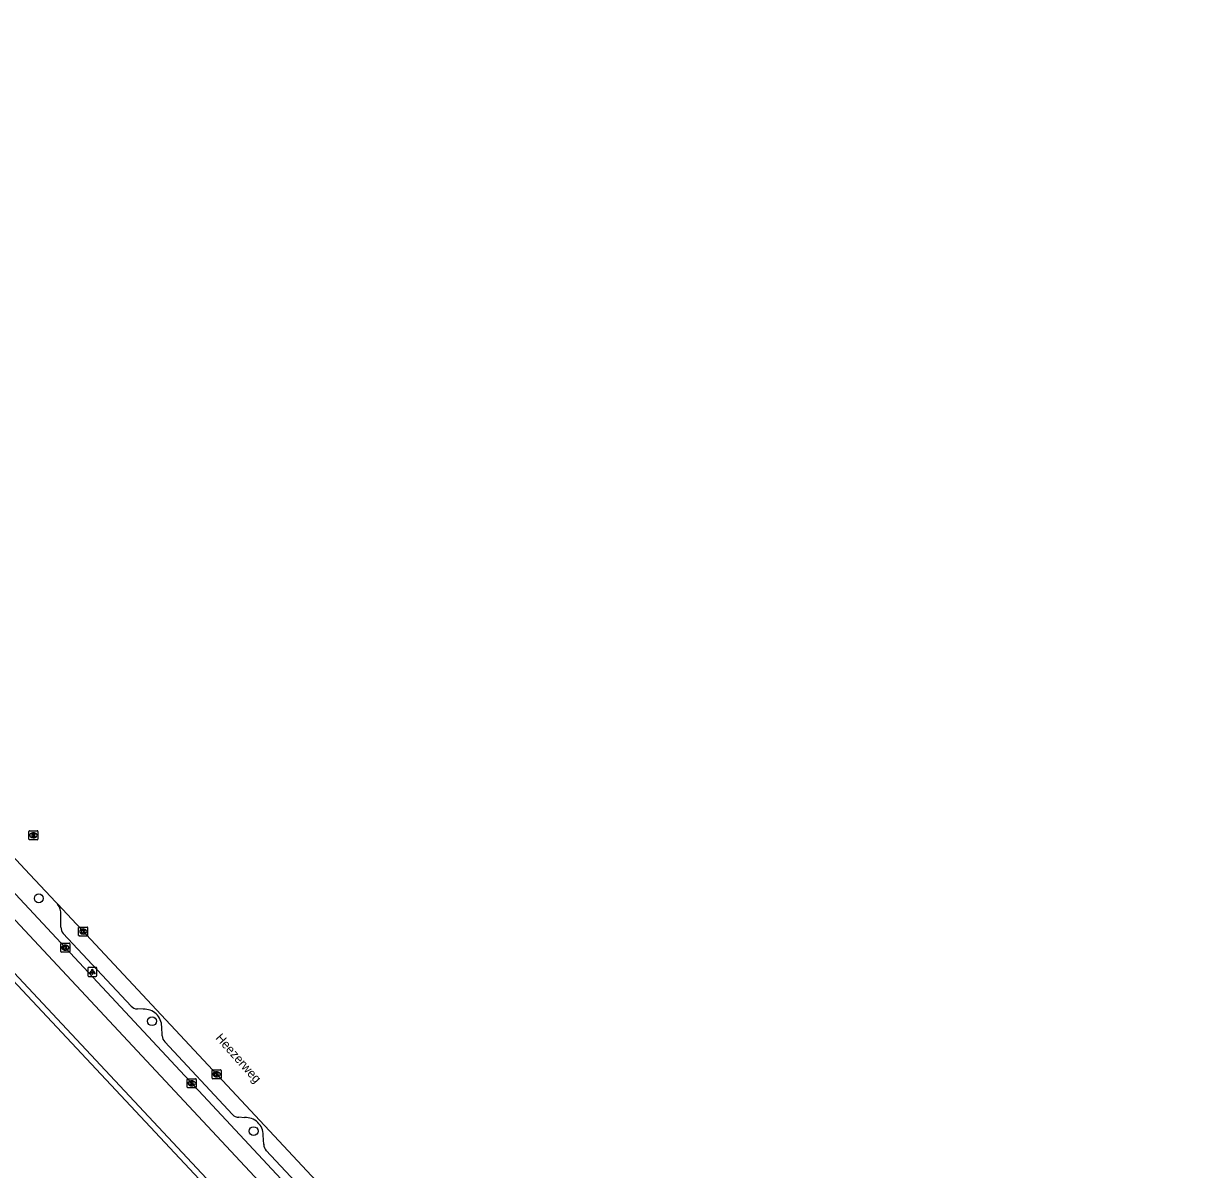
# Model space of a CAD drawing. Extents: x 162675 to 163482, y 379761 to 381227.
# Drawn here: x 163311.1 to 163442.5, y 381014.2 to 381141.4 of the extents above; entities that cross this region are included whole.
import ezdxf

# ---------------------------------------------------------------- set-up
doc = ezdxf.new("R2010")
doc.units = 0
for name, color, linetype in [('IMGEO_Boom', 7, 'Continuous'), ('IMGEO_Fietspad_gesloten', 7, 'Continuous'), ('IMGEO_Groenvoorziening', 7, 'Continuous'), ('IMGEO_Kolk', 7, 'Continuous'), ('IMGEO_Lichtpunt', 7, 'Continuous'), ('IMGEO_Openbare_ruimte_label', 7, 'Continuous'), ('IMGEO_Parkeervlak_open', 7, 'Continuous'), ('IMGEO_Rijbaan_lokaal_gesloten', 7, 'Continuous'), ('IMGEO_Rioolput', 7, 'Continuous'), ('IMGEO_Voetpad_open', 7, 'Continuous')]:
    doc.layers.add(name, color=color, linetype=linetype)

msp = doc.modelspace()

# ---------------------------------------------------------------- linework, layer by layer
at = {"layer": 'IMGEO_Boom'}
for centre in [(163312.75, 381044.24), (163325.33, 381030.6), (163336.61, 381018.4)]:
    msp.add_circle(centre, 0.489, dxfattribs=at)
at = {"layer": 'IMGEO_Fietspad_gesloten'}
for points in [[(163442.53, 380900.21), (163438.58, 380904.4), (163403.36, 380942.04), (163381.32, 380965.64), (163349.19, 381000), (163303.35, 381049.03), (163302.54, 381049.9), (163269.7, 381085.15), (163222.96, 381135.12), (163217.06, 381141.36)], [(163297.63, 381058.04), (163301.94, 381053.48), (163304.04, 381051.23), (163315.71, 381038.75), (163343.73, 381008.7), (163351.89, 381000), (163369.83, 380980.88), (163383.5, 380966.22), (163404.83, 380943.42), (163407.34, 380940.66), (163420.71, 380926.42), (163421.99, 380925.07)]]:
    msp.add_lwpolyline(points, dxfattribs=at)
at = {"layer": 'IMGEO_Groenvoorziening'}
msp.add_lwpolyline([(163366.04, 380975.19), (163307.1, 381038.09), (163305.72, 381038.49), (163302.71, 381038.33)], dxfattribs=at)
at = {"layer": 'IMGEO_Kolk'}
for p, q in [((163317.18, 381040.13), (163317.18, 381040.99)), ((163317.26, 381041.06), (163318.11, 381041.06)), ((163318.11, 381040.06), (163317.26, 381040.06)), ((163317.67, 381040.84), (163317.7, 381040.84)), ((163317.69, 381040.28), (163317.67, 381040.28)), ((163318.18, 381040.99), (163318.18, 381040.13)), ((163315.19, 381038.34), (163315.19, 381039.2)), ((163315.27, 381039.27), (163316.12, 381039.27)), ((163315.68, 381039.05), (163315.71, 381039.05)), ((163316.19, 381039.2), (163316.19, 381038.34)), ((163316.12, 381038.27), (163315.27, 381038.27)), ((163315.7, 381038.49), (163315.68, 381038.49)), ((163332, 381024.29), (163332, 381025.14)), ((163332.07, 381025.21), (163332.93, 381025.21)), ((163332.51, 381024.43), (163332.48, 381024.43)), ((163332.49, 381024.99), (163332.51, 381024.99)), ((163333, 381025.14), (163333, 381024.29)), ((163329.23, 381023.28), (163329.23, 381024.14)), ((163329.31, 381024.21), (163330.16, 381024.21)), ((163330.16, 381023.21), (163329.31, 381023.21)), ((163329.72, 381023.99), (163329.75, 381023.99)), ((163329.74, 381023.43), (163329.72, 381023.43)), ((163330.24, 381024.14), (163330.24, 381023.28)), ((163332.93, 381024.21), (163332.07, 381024.21))]:
    msp.add_line(p, q, dxfattribs=at)
for points in [[(163317.18, 381040.13), (163317.18, 381040.99)], [(163317.26, 381041.06), (163318.11, 381041.06)], [(163318.11, 381040.06), (163317.26, 381040.06)], [(163317.5, 381040.76), (163317.63, 381040.76), (163317.63, 381040.61), (163317.76, 381040.76), (163317.92, 381040.76), (163317.78, 381040.61), (163317.93, 381040.36), (163317.78, 381040.36), (163317.69, 381040.52), (163317.63, 381040.46), (163317.63, 381040.36), (163317.5, 381040.36), (163317.5, 381040.76)], [(163318.18, 381040.99), (163318.18, 381040.13)], [(163315.19, 381038.34), (163315.19, 381039.2)], [(163315.27, 381039.27), (163316.12, 381039.27)], [(163315.51, 381038.97), (163315.64, 381038.97), (163315.64, 381038.82), (163315.77, 381038.97), (163315.93, 381038.97), (163315.78, 381038.82), (163315.94, 381038.57), (163315.78, 381038.57), (163315.7, 381038.74), (163315.64, 381038.67), (163315.64, 381038.57), (163315.51, 381038.57), (163315.51, 381038.97)], [(163316.19, 381039.2), (163316.19, 381038.34)], [(163316.12, 381038.27), (163315.27, 381038.27)], [(163332, 381024.29), (163332, 381025.14)], [(163332.07, 381025.21), (163332.93, 381025.21)], [(163332.32, 381024.91), (163332.44, 381024.91), (163332.44, 381024.76), (163332.57, 381024.91), (163332.74, 381024.91), (163332.59, 381024.76), (163332.74, 381024.51), (163332.59, 381024.51), (163332.51, 381024.68), (163332.44, 381024.61), (163332.44, 381024.51), (163332.32, 381024.51), (163332.32, 381024.91)], [(163333, 381025.14), (163333, 381024.29)], [(163329.23, 381023.28), (163329.23, 381024.14)], [(163329.31, 381024.21), (163330.16, 381024.21)], [(163330.16, 381023.21), (163329.31, 381023.21)], [(163329.55, 381023.91), (163329.68, 381023.91), (163329.68, 381023.76), (163329.81, 381023.91), (163329.97, 381023.91), (163329.83, 381023.76), (163329.98, 381023.51), (163329.83, 381023.51), (163329.74, 381023.68), (163329.68, 381023.61), (163329.68, 381023.51), (163329.55, 381023.51), (163329.55, 381023.91)], [(163330.24, 381024.14), (163330.24, 381023.28)], [(163332.93, 381024.21), (163332.07, 381024.21)]]:
    msp.add_lwpolyline(points, dxfattribs=at)
for centre, start, end in [((163317.26, 381040.98), 91.552, 178.448), ((163317.26, 381040.98), 91.552, 178.448), ((163317.26, 381040.14), 181.552, 268.448), ((163317.26, 381040.14), 181.552, 268.448), ((163318.11, 381040.98), 1.552, 88.448), ((163318.11, 381040.98), 1.552, 88.448), ((163318.11, 381040.14), 271.552, 358.448), ((163318.11, 381040.14), 271.552, 358.448), ((163315.27, 381039.2), 91.552, 178.448), ((163315.27, 381039.2), 91.552, 178.448), ((163316.12, 381039.2), 1.552, 88.448), ((163316.12, 381039.2), 1.552, 88.448), ((163315.27, 381038.35), 181.552, 268.448), ((163315.27, 381038.35), 181.552, 268.448), ((163316.12, 381038.35), 271.552, 358.448), ((163316.12, 381038.35), 271.552, 358.448), ((163332.07, 381025.14), 91.552, 178.448), ((163332.07, 381025.14), 91.552, 178.448), ((163332.07, 381024.29), 181.552, 268.448), ((163332.07, 381024.29), 181.552, 268.448), ((163332.92, 381025.14), 1.552, 88.448), ((163332.92, 381025.14), 1.552, 88.448), ((163332.92, 381024.29), 271.552, 358.448), ((163332.92, 381024.29), 271.552, 358.448), ((163329.31, 381024.14), 91.552, 178.448), ((163329.31, 381024.14), 91.552, 178.448), ((163329.31, 381023.29), 181.552, 268.448), ((163329.31, 381023.29), 181.552, 268.448), ((163330.16, 381024.14), 1.552, 88.448), ((163330.16, 381024.14), 1.552, 88.448), ((163330.16, 381023.29), 271.552, 358.448), ((163330.16, 381023.29), 271.552, 358.448)]:
    msp.add_arc(centre, 0.0765, start, end, dxfattribs=at)
for centre, major_axis, ratio, start_param, end_param in [((163317.67, 381040.56), (-0.387, 0.002), 0.722429, 4.712389, 7.853982), ((163317.69, 381040.56), (-0.39, 0.002), 0.717154, 1.570796, 4.712389), ((163315.68, 381038.77), (-0.387, 0.002), 0.722429, 4.712389, 7.853982), ((163315.7, 381038.77), (-0.39, 0.002), 0.717154, 1.570796, 4.712389), ((163332.49, 381024.71), (-0.387, 0.002), 0.722429, 4.712389, 7.853982), ((163332.51, 381024.71), (-0.39, 0.002), 0.717154, 1.570796, 4.712389), ((163329.72, 381023.71), (-0.387, 0.002), 0.722429, 4.712389, 7.853982), ((163329.75, 381023.71), (-0.39, 0.002), 0.717154, 1.570796, 4.712389)]:
    msp.add_ellipse(centre, major_axis=major_axis, ratio=ratio, start_param=start_param, end_param=end_param, dxfattribs=at)
at = {"layer": 'IMGEO_Lichtpunt'}
for p, q in [((163318.2, 381036.48), (163318.2, 381035.68)), ((163318.2, 381036.48), (163318.2, 381035.68)), ((163319.1, 381036.58), (163318.29, 381036.58)), ((163319.1, 381036.58), (163318.29, 381036.58)), ((163319.2, 381035.68), (163319.2, 381036.48)), ((163319.2, 381035.68), (163319.2, 381036.48)), ((163318.29, 381035.58), (163319.1, 381035.58)), ((163318.29, 381035.58), (163319.1, 381035.58))]:
    msp.add_line(p, q, dxfattribs=at)
for points in [[(163318.57, 381036.15), (163318.61, 381036.12), (163318.42, 381035.86), (163318.39, 381035.89), (163318.57, 381036.15)], [(163318.67, 381036.1), (163318.72, 381036.1), (163318.72, 381035.78), (163318.67, 381035.78), (163318.67, 381036.1)], [(163318.78, 381036.12), (163318.82, 381036.15), (163319.01, 381035.88), (163318.97, 381035.86), (163318.78, 381036.12)]]:
    msp.add_lwpolyline(points, dxfattribs=at)
msp.add_circle((163318.7, 381036.28), 0.0994, dxfattribs=at)
for centre, start, end in [((163318.29, 381036.48), 90, 180), ((163318.29, 381036.48), 90, 180), ((163319.1, 381036.48), 0, 90), ((163319.1, 381036.48), 0, 90), ((163318.29, 381035.68), 180, 270), ((163318.29, 381035.68), 180, 270), ((163319.1, 381035.68), 270, 0), ((163319.1, 381035.68), 270, 360)]:
    msp.add_arc(centre, 0.0946, start, end, dxfattribs=at)
at = {"layer": 'IMGEO_Parkeervlak_open'}
for points in [[(163315.21, 381041.06), (163315.2, 381042.41)], [(163323, 381032.28), (163315.45, 381040.35)], [(163324.36, 381031.95), (163323.71, 381031.97)], [(163326.46, 381028.99), (163326.42, 381030.01)], [(163334.27, 381020.25), (163326.74, 381028.3)], [(163335.61, 381019.89), (163334.97, 381019.93)], [(163337.73, 381016.93), (163337.68, 381017.95)], [(163345.54, 381008.17), (163338.01, 381016.23)]]:
    msp.add_lwpolyline(points, dxfattribs=at)
for centre, radius, start, end in [((163313.52, 381042.55), 1.69, 355.2918, 38.1777), ((163316.21, 381041), 0.997, 176.5621, 220.8381), ((163323.7, 381032.91), 0.944, 222.181, 270.2873), ((163324.44, 381029.97), 1.97, 1.0164, 92.5348), ((163327.51, 381029.01), 1.04, 181.1399, 222.6931), ((163334.93, 381020.77), 0.837, 217.8841, 272.5864), ((163335.73, 381017.95), 1.95, 359.8404, 93.612), ((163338.93, 381017), 1.2, 183.1766, 220.119)]:
    msp.add_arc(centre, radius, start, end, dxfattribs=at)
at = {"layer": 'IMGEO_Rijbaan_lokaal_gesloten'}
for points in [[(163299.08, 381060.41), (163304.11, 381055.04), (163306.04, 381053.02), (163306.58, 381052.45), (163311.19, 381047.48), (163314.65, 381043.81), (163314.85, 381043.59)], [(163314.85, 381043.59), (163355.6, 381000), (163371.21, 380983.31)]]:
    msp.add_lwpolyline(points, dxfattribs=at)
at = {"layer": 'IMGEO_Rioolput'}
for p, q in [((163311.66, 381050.82), (163311.66, 381051.68)), ((163311.73, 381051.75), (163312.58, 381051.75)), ((163312.58, 381050.75), (163311.73, 381050.75)), ((163312.17, 381050.97), (163312.14, 381050.97)), ((163312.15, 381051.53), (163312.17, 381051.53)), ((163312.66, 381051.68), (163312.66, 381050.82))]:
    msp.add_line(p, q, dxfattribs=at)
for points in [[(163311.66, 381050.82), (163311.66, 381051.68)], [(163311.73, 381051.75), (163312.58, 381051.75)], [(163312.58, 381050.75), (163311.73, 381050.75)], [(163312.25, 381051.45), (163311.99, 381051.45), (163311.99, 381051.05)], [(163311.99, 381051.05), (163312.12, 381051.05), (163312.12, 381051.21), (163312.13, 381051.21)], [(163312.17, 381051.37), (163312.12, 381051.37), (163312.12, 381051.29)], [(163312.12, 381051.29), (163312.17, 381051.29)], [(163312.18, 381051.18), (163312.25, 381051.05), (163312.39, 381051.05), (163312.32, 381051.18)], [(163312.66, 381051.68), (163312.66, 381050.82)]]:
    msp.add_lwpolyline(points, dxfattribs=at)
for centre, radius, start, end in [((163311.73, 381051.67), 0.0765, 91.552, 178.448), ((163311.73, 381051.67), 0.0765, 91.552, 178.448), ((163311.73, 381050.83), 0.0765, 181.552, 268.448), ((163311.73, 381050.83), 0.0765, 181.552, 268.448), ((163312.13, 381051.16), 0.0533, 26.0293, 88.6989), ((163312.18, 381051.27), 0.0964, 77.0061, 93.1865), ((163312.15, 381051.48), 0.19, 274.7715, 282.9687), ((163312.19, 381051.33), 0.0378, 276.6634, 79.6772), ((163312.25, 381051.34), 0.109, 350.3612, 89.416), ((163312.24, 381051.34), 0.112, 277.5842, 350.9817), ((163312.23, 381051.12), 0.108, 29.5134, 73.7905), ((163312.58, 381051.67), 0.0765, 1.552, 88.448), ((163312.58, 381051.67), 0.0765, 1.552, 88.448), ((163312.58, 381050.83), 0.0765, 271.552, 358.448), ((163312.58, 381050.83), 0.0765, 271.552, 358.448)]:
    msp.add_arc(centre, radius, start, end, dxfattribs=at)
for centre, major_axis, ratio, start_param, end_param in [((163312.14, 381051.25), (-0.387, 0.002), 0.722429, 4.712389, 7.853982), ((163312.17, 381051.25), (-0.39, 0.002), 0.717154, 1.570796, 4.712389)]:
    msp.add_ellipse(centre, major_axis=major_axis, ratio=ratio, start_param=start_param, end_param=end_param, dxfattribs=at)
at = {"layer": 'IMGEO_Voetpad_open'}
msp.add_lwpolyline([(163304.46, 381041.87), (163308.35, 381037.72), (163343.65, 381000), (163361.77, 380980.64)], dxfattribs=at)

# ---------------------------------------------------------------- texts
at = {"layer": 'IMGEO_Openbare_ruimte_label'}
msp.add_text('Heezerweg', height=1, rotation=311.5955, dxfattribs=at).set_placement((163332.32, 381028.7))

doc.saveas('drawing.dxf')
